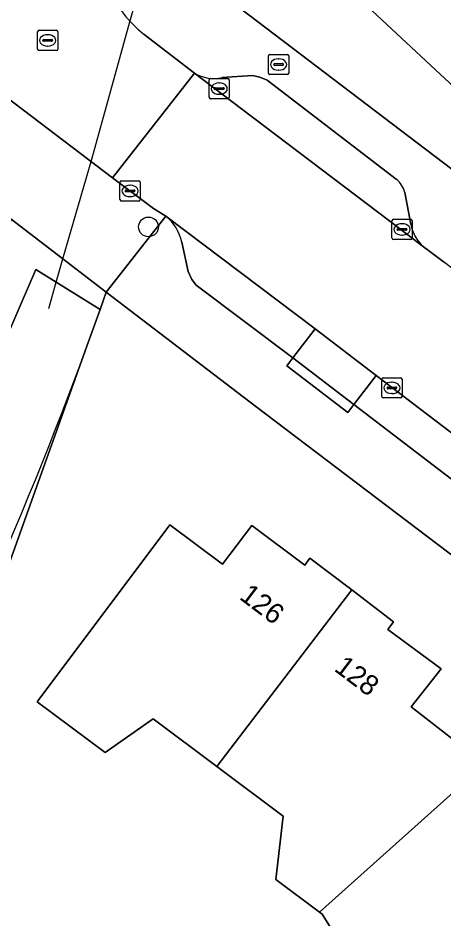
# Model space of a CAD drawing. Extents: x 159626 to 160723, y 388173 to 389416.
# Drawn here: x 160440.65 to 160461.73, y 388606.29 to 388650.92 of the extents above; entities that cross this region are included whole.
import ezdxf

# ---------------------------------------------------------------- set-up
doc = ezdxf.new("R2010")
doc.units = 0
for name, color, linetype in [('IMGEO_Berm_groen', 7, 'Continuous'), ('IMGEO_Boom', 7, 'Continuous'), ('IMGEO_Brandkraan', 7, 'Continuous'), ('IMGEO_Duiker', 7, 'Continuous'), ('IMGEO_Erf', 7, 'Continuous'), ('IMGEO_Kolk', 7, 'Continuous'), ('IMGEO_Pand', 7, 'Continuous'), ('IMGEO_Pand_nummerreeks', 7, 'Continuous'), ('IMGEO_Parkeervlak_open', 7, 'Continuous'), ('IMGEO_Rijbaan_lokaal_gesloten', 7, 'Continuous'), ('IMGEO_Rijbaan_lokaal_open', 7, 'Continuous'), ('IMGEO_Rioolput', 7, 'Continuous'), ('IMGEO_Voetpad_open', 7, 'Continuous'), ('IMGEO_Waterloop', 7, 'Continuous')]:
    doc.layers.add(name, color=color, linetype=linetype)

msp = doc.modelspace()

# ---------------------------------------------------------------- linework, layer by layer
at = {"layer": 'IMGEO_Berm_groen'}
for points in [[(160429.634, 388610.908), (160441.529, 388638.466), (160442.538, 388637.837), (160444.706, 388636.484), (160445.015, 388637.348), (160442.866, 388638.996), (160440.306, 388640.958), (160440.14, 388640.514), (160439.973, 388640.071)], [(160426.76, 388595.873), (160434.06, 388609.33), (160439.82, 388622.82), (160444.055, 388634.663)]]:
    msp.add_lwpolyline(points, dxfattribs=at)
msp.add_arc((160271.208, 388697.491), 183.911, 331.19029, 340.02424, dxfattribs=at)
at = {"layer": 'IMGEO_Boom'}
msp.add_circle((160447.102, 388640.575), 0.489, dxfattribs=at)
at = {"layer": 'IMGEO_Brandkraan'}
for p, q in [((160453.041, 388648.195), (160453.041, 388649.047)), ((160453.116, 388649.121), (160453.968, 388649.121)), ((160453.529, 388648.901), (160453.554, 388648.901)), ((160454.042, 388649.047), (160454.042, 388648.195)), ((160453.3, 388648.615), (160453.3, 388648.627)), ((160453.738, 388648.578), (160453.34, 388648.578)), ((160453.343, 388648.664), (160453.741, 388648.664)), ((160453.552, 388648.341), (160453.527, 388648.341)), ((160453.784, 388648.627), (160453.784, 388648.615)), ((160453.968, 388648.121), (160453.116, 388648.121))]:
    msp.add_line(p, q, dxfattribs=at)
for points in [[(160453.041, 388648.195), (160453.041, 388649.047)], [(160453.116, 388649.121), (160453.968, 388649.121)], [(160454.042, 388649.047), (160454.042, 388648.195)], [(160453.968, 388648.121), (160453.116, 388648.121)]]:
    msp.add_lwpolyline(points, dxfattribs=at)
for centre, radius, start, end in [((160453.118, 388649.045), 0.0765, 91.552, 178.448), ((160453.118, 388649.045), 0.0765, 91.552, 178.448), ((160453.966, 388649.045), 0.0765, 1.552, 88.448), ((160453.966, 388649.045), 0.0765, 1.552, 88.448), ((160453.34, 388648.624), 0.0403, 85.8775, 175.7526), ((160453.337, 388648.614), 0.0366, 178.938, 274.7102), ((160453.741, 388648.621), 0.043, 264.8664, 352.4533), ((160453.745, 388648.626), 0.0386, 1.7309, 96.639), ((160453.118, 388648.197), 0.0765, 181.552, 268.448), ((160453.118, 388648.197), 0.0765, 181.552, 268.448), ((160453.966, 388648.197), 0.0765, 271.552, 358.448), ((160453.966, 388648.197), 0.0765, 271.552, 358.448)]:
    msp.add_arc(centre, radius, start, end, dxfattribs=at)
for centre, major_axis, ratio, start_param, end_param in [((160453.528, 388648.621), (-0.387, 0.002), 0.722429, 4.712389, 7.853982), ((160453.553, 388648.621), (-0.39, 0.002), 0.717154, 1.570796, 4.712389)]:
    msp.add_ellipse(centre, major_axis=major_axis, ratio=ratio, start_param=start_param, end_param=end_param, dxfattribs=at)
at = {"layer": 'IMGEO_Duiker'}
msp.add_lwpolyline([(160442.168, 388636.53), (160442.538, 388637.837), (160442.866, 388638.996), (160444.292, 388643.932), (160446.185, 388650.731), (160447.311, 388654.712), (160447.539, 388655.517), (160447.651, 388655.912)], dxfattribs=at)
at = {"layer": 'IMGEO_Erf'}
for points in [[(160464.967, 388644.948), (160461.313, 388648.361), (160455.028, 388654.227), (160460.023, 388659.588), (160459.203, 388660.352), (160462.612, 388664.011)], [(160448.508, 388655.087), (160448.24, 388654.005), (160450.027, 388652.645), (160464.587, 388641.545)], [(160473.922, 388615.363), (160452.411, 388631.678), (160445.015, 388637.348), (160444.706, 388636.484), (160444.055, 388634.663), (160439.82, 388622.82), (160434.06, 388609.33), (160426.76, 388595.873), (160418.317, 388583.095), (160421.291, 388580.817), (160422.334, 388579.975)], [(160462.556, 388600.786), (160460.41, 388604.216), (160457.583, 388603.522), (160455.705, 388606.522), (160455.569, 388606.624), (160453.408, 388608.239), (160453.774, 388611.386), (160450.491, 388613.842), (160447.336, 388616.202), (160444.953, 388614.537), (160441.598, 388617.047), (160448.158, 388625.814), (160450.768, 388623.86), (160452.211, 388625.789), (160454.837, 388623.823), (160455.094, 388624.167), (160457.163, 388622.589), (160459.23, 388621.012), (160458.945, 388620.624), (160461.592, 388618.682), (160460.1, 388616.798), (160463.747, 388613.959)]]:
    msp.add_lwpolyline(points, dxfattribs=at)
at = {"layer": 'IMGEO_Kolk'}
for p, q in [((160450.102, 388647.001), (160450.102, 388647.853)), ((160450.177, 388647.927), (160451.029, 388647.927)), ((160451.103, 388647.853), (160451.103, 388647.001)), ((160450.361, 388647.421), (160450.361, 388647.433)), ((160450.799, 388647.384), (160450.401, 388647.384)), ((160450.404, 388647.47), (160450.802, 388647.47)), ((160450.59, 388647.707), (160450.615, 388647.707)), ((160450.845, 388647.433), (160450.845, 388647.421)), ((160451.029, 388646.927), (160450.177, 388646.927)), ((160450.613, 388647.147), (160450.588, 388647.147)), ((160445.69, 388641.932), (160445.69, 388642.784)), ((160445.765, 388642.858), (160446.617, 388642.858)), ((160446.178, 388642.638), (160446.203, 388642.638)), ((160446.691, 388642.784), (160446.691, 388641.932)), ((160445.949, 388642.352), (160445.949, 388642.364)), ((160446.387, 388642.315), (160445.989, 388642.315)), ((160445.992, 388642.401), (160446.39, 388642.401)), ((160446.201, 388642.078), (160446.176, 388642.078)), ((160446.433, 388642.364), (160446.433, 388642.352)), ((160446.617, 388641.858), (160445.765, 388641.858)), ((160459.152, 388640.026), (160459.152, 388640.878)), ((160459.227, 388640.952), (160460.079, 388640.952)), ((160459.64, 388640.732), (160459.665, 388640.732)), ((160460.153, 388640.878), (160460.153, 388640.026)), ((160459.411, 388640.446), (160459.411, 388640.458)), ((160459.849, 388640.409), (160459.451, 388640.409)), ((160459.454, 388640.495), (160459.852, 388640.495)), ((160459.895, 388640.458), (160459.895, 388640.446)), ((160460.079, 388639.952), (160459.227, 388639.952)), ((160459.663, 388640.172), (160459.638, 388640.172)), ((160458.725, 388633.1), (160459.577, 388633.1)), ((160458.65, 388632.174), (160458.65, 388633.026)), ((160458.952, 388632.643), (160459.35, 388632.643)), ((160459.138, 388632.88), (160459.163, 388632.88)), ((160459.651, 388633.026), (160459.651, 388632.174)), ((160458.909, 388632.594), (160458.909, 388632.606)), ((160459.347, 388632.557), (160458.949, 388632.557)), ((160459.161, 388632.32), (160459.136, 388632.32)), ((160459.393, 388632.606), (160459.393, 388632.594)), ((160459.577, 388632.1), (160458.725, 388632.1))]:
    msp.add_line(p, q, dxfattribs=at)
for points in [[(160450.102, 388647.001), (160450.102, 388647.853)], [(160450.177, 388647.927), (160451.029, 388647.927)], [(160451.103, 388647.853), (160451.103, 388647.001)], [(160451.029, 388646.927), (160450.177, 388646.927)], [(160445.69, 388641.932), (160445.69, 388642.784)], [(160445.765, 388642.858), (160446.617, 388642.858)], [(160446.691, 388642.784), (160446.691, 388641.932)], [(160446.617, 388641.858), (160445.765, 388641.858)], [(160459.152, 388640.026), (160459.152, 388640.878)], [(160459.227, 388640.952), (160460.079, 388640.952)], [(160460.153, 388640.878), (160460.153, 388640.026)], [(160460.079, 388639.952), (160459.227, 388639.952)], [(160458.725, 388633.1), (160459.577, 388633.1)], [(160458.65, 388632.174), (160458.65, 388633.026)], [(160459.651, 388633.026), (160459.651, 388632.174)], [(160459.577, 388632.1), (160458.725, 388632.1)]]:
    msp.add_lwpolyline(points, dxfattribs=at)
for centre, radius, start, end in [((160450.179, 388647.851), 0.0765, 91.552, 178.448), ((160450.179, 388647.851), 0.0765, 91.552, 178.448), ((160451.027, 388647.851), 0.0765, 1.552, 88.448), ((160451.027, 388647.851), 0.0765, 1.552, 88.448), ((160450.401, 388647.43), 0.0403, 85.8775, 175.7526), ((160450.398, 388647.42), 0.0366, 178.938, 274.7102), ((160450.802, 388647.427), 0.043, 264.8664, 352.4533), ((160450.806, 388647.432), 0.0386, 1.7309, 96.639), ((160450.179, 388647.003), 0.0765, 181.552, 268.448), ((160450.179, 388647.003), 0.0765, 181.552, 268.448), ((160451.027, 388647.003), 0.0765, 271.552, 358.448), ((160451.027, 388647.003), 0.0765, 271.552, 358.448), ((160445.767, 388642.782), 0.0765, 91.552, 178.448), ((160445.767, 388642.782), 0.0765, 91.552, 178.448), ((160446.615, 388642.782), 0.0765, 1.552, 88.448), ((160446.615, 388642.782), 0.0765, 1.552, 88.448), ((160445.989, 388642.361), 0.0403, 85.8775, 175.7526), ((160445.986, 388642.351), 0.0366, 178.938, 274.7102), ((160446.39, 388642.358), 0.043, 264.8664, 352.4533), ((160446.394, 388642.363), 0.0386, 1.7309, 96.639), ((160445.767, 388641.934), 0.0765, 181.552, 268.448), ((160445.767, 388641.934), 0.0765, 181.552, 268.448), ((160446.615, 388641.934), 0.0765, 271.552, 358.448), ((160446.615, 388641.934), 0.0765, 271.552, 358.448), ((160459.229, 388640.876), 0.0765, 91.552, 178.448), ((160459.229, 388640.876), 0.0765, 91.552, 178.448), ((160460.077, 388640.876), 0.0765, 1.552, 88.448), ((160460.077, 388640.876), 0.0765, 1.552, 88.448), ((160459.451, 388640.455), 0.0403, 85.8775, 175.7526), ((160459.448, 388640.445), 0.0366, 178.938, 274.7102), ((160459.852, 388640.452), 0.043, 264.8664, 352.4533), ((160459.856, 388640.457), 0.0386, 1.7309, 96.639), ((160459.229, 388640.028), 0.0765, 181.552, 268.448), ((160459.229, 388640.028), 0.0765, 181.552, 268.448), ((160460.077, 388640.028), 0.0765, 271.552, 358.448), ((160460.077, 388640.028), 0.0765, 271.552, 358.448), ((160458.727, 388633.024), 0.0765, 91.552, 178.448), ((160458.727, 388633.024), 0.0765, 91.552, 178.448), ((160459.575, 388633.024), 0.0765, 1.552, 88.448), ((160459.575, 388633.024), 0.0765, 1.552, 88.448), ((160458.949, 388632.603), 0.0403, 85.8775, 175.7526), ((160459.354, 388632.605), 0.0386, 1.7309, 96.639), ((160458.946, 388632.593), 0.0366, 178.938, 274.7102), ((160459.35, 388632.6), 0.043, 264.8664, 352.4533), ((160458.727, 388632.176), 0.0765, 181.552, 268.448), ((160458.727, 388632.176), 0.0765, 181.552, 268.448), ((160459.575, 388632.176), 0.0765, 271.552, 358.448), ((160459.575, 388632.176), 0.0765, 271.552, 358.448)]:
    msp.add_arc(centre, radius, start, end, dxfattribs=at)
for centre, major_axis, ratio, start_param, end_param in [((160450.589, 388647.427), (-0.387, 0.002), 0.722429, 4.712389, 7.853982), ((160450.614, 388647.427), (-0.39, 0.002), 0.717154, 1.570796, 4.712389), ((160446.177, 388642.358), (-0.387, 0.002), 0.722429, 4.712389, 7.853982), ((160446.202, 388642.358), (-0.39, 0.002), 0.717154, 1.570796, 4.712389), ((160459.639, 388640.452), (-0.387, 0.002), 0.722429, 4.712389, 7.853982), ((160459.664, 388640.452), (-0.39, 0.002), 0.717154, 1.570796, 4.712389), ((160459.137, 388632.6), (-0.387, 0.002), 0.722429, 4.712389, 7.853982), ((160459.162, 388632.6), (-0.39, 0.002), 0.717154, 1.570796, 4.712389)]:
    msp.add_ellipse(centre, major_axis=major_axis, ratio=ratio, start_param=start_param, end_param=end_param, dxfattribs=at)
at = {"layer": 'IMGEO_Pand'}
for points in [[(160471.835, 388655.659), (160471.955, 388655.754), (160462.835, 388664.25), (160462.612, 388664.011), (160459.203, 388660.352), (160460.023, 388659.588), (160455.028, 388654.227), (160461.313, 388648.361), (160464.967, 388644.948), (160470.181, 388650.532), (160468.521, 388652.097), (160470.903, 388654.657)], [(160450.491, 388613.842), (160457.163, 388622.589), (160455.094, 388624.167), (160454.837, 388623.823), (160452.211, 388625.789), (160450.768, 388623.86), (160448.158, 388625.814), (160441.598, 388617.047), (160444.953, 388614.537), (160447.336, 388616.202)], [(160450.491, 388613.842), (160453.774, 388611.386), (160453.408, 388608.239), (160455.569, 388606.624), (160463.747, 388613.959), (160460.1, 388616.798), (160461.592, 388618.682), (160458.945, 388620.624), (160459.23, 388621.012), (160457.163, 388622.589)], [(160463.747, 388613.959), (160455.569, 388606.624), (160455.705, 388606.522), (160457.583, 388603.522), (160460.41, 388604.216), (160462.556, 388600.786), (160471.743, 388606.531), (160470.359, 388608.742), (160469.995, 388608.514), (160468.256, 388611.295), (160466.213, 388610.017)]]:
    msp.add_lwpolyline(points, close=True, dxfattribs=at)
at = {"layer": 'IMGEO_Parkeervlak_open'}
for points in [[(160449.379, 388648.196), (160451.702, 388646.423), (160459.596, 388640.453), (160460.712, 388639.589)], [(160459.361, 388642.94), (160452.979, 388647.838), (160452.614, 388647.988), (160452.258, 388648.07), (160450.745, 388647.969)], [(160460.082, 388640.712), (160459.789, 388642.287)], [(160448.745, 388639.816), (160449.059, 388638.37), (160449.24, 388637.977), (160449.456, 388637.696), (160454.246, 388634.083), (160455.348, 388635.527), (160447.964, 388641.112)]]:
    msp.add_lwpolyline(points, dxfattribs=at)
for points in [[(160455.348, 388635.527), (160454.246, 388634.083), (160457.268, 388631.77), (160458.374, 388633.219)], [(160458.374, 388633.219), (160457.268, 388631.77), (160466.036, 388625.067), (160467.149, 388626.526)]]:
    msp.add_lwpolyline(points, close=True, dxfattribs=at)
for centre, radius, start, end in [((160450.339, 388649.748), 1.825, 238.267, 282.8627), ((160458.629, 388641.993), 1.197, 14.2044, 52.2802), ((160446.513, 388639.354), 2.279, 11.6885, 50.4598), ((160462.065, 388641.086), 2.018, 190.6917, 227.8929)]:
    msp.add_arc(centre, radius, start, end, dxfattribs=at)
at = {"layer": 'IMGEO_Rijbaan_lokaal_gesloten'}
msp.add_lwpolyline([(160480.726, 388624.386), (160479.761, 388625.134), (160479.475, 388625.34), (160463.293, 388637.64), (160461.761, 388638.812), (160460.956, 388639.4), (160460.712, 388639.589), (160459.596, 388640.453), (160451.702, 388646.423), (160449.379, 388648.196), (160445.327, 388643.009), (160447.348, 388641.481), (160447.964, 388641.112), (160455.348, 388635.527), (160458.374, 388633.219), (160467.149, 388626.526), (160470.17, 388624.222), (160475.385, 388620.244), (160477.279, 388618.799)], dxfattribs=at)
at = {"layer": 'IMGEO_Rijbaan_lokaal_open'}
msp.add_lwpolyline([(160435.247, 388658.875), (160434.926, 388659.154), (160430.911, 388653.976), (160445.327, 388643.009), (160449.379, 388648.196), (160446.896, 388650.101)], dxfattribs=at)
msp.add_arc((160450.597, 388654.787), 5.971, 168.5893, 231.6965, dxfattribs=at)
at = {"layer": 'IMGEO_Rioolput'}
for p, q in [((160441.612, 388649.388), (160441.612, 388650.24)), ((160441.687, 388650.314), (160442.539, 388650.314)), ((160442.1, 388650.094), (160442.125, 388650.094)), ((160442.613, 388650.24), (160442.613, 388649.388)), ((160441.871, 388649.808), (160441.871, 388649.82)), ((160442.309, 388649.771), (160441.911, 388649.771)), ((160441.914, 388649.857), (160442.312, 388649.857)), ((160442.355, 388649.82), (160442.355, 388649.808)), ((160442.539, 388649.314), (160441.687, 388649.314)), ((160442.123, 388649.534), (160442.098, 388649.534))]:
    msp.add_line(p, q, dxfattribs=at)
for points in [[(160441.612, 388649.388), (160441.612, 388650.24)], [(160441.687, 388650.314), (160442.539, 388650.314)], [(160442.613, 388650.24), (160442.613, 388649.388)], [(160442.539, 388649.314), (160441.687, 388649.314)]]:
    msp.add_lwpolyline(points, dxfattribs=at)
for centre, radius, start, end in [((160441.689, 388650.238), 0.0765, 91.552, 178.448), ((160441.689, 388650.238), 0.0765, 91.552, 178.448), ((160442.537, 388650.238), 0.0765, 1.552, 88.448), ((160442.537, 388650.238), 0.0765, 1.552, 88.448), ((160441.911, 388649.817), 0.0403, 85.8775, 175.7526), ((160441.908, 388649.807), 0.0366, 178.938, 274.7102), ((160442.312, 388649.814), 0.043, 264.8664, 352.4533), ((160442.316, 388649.819), 0.0386, 1.7309, 96.639), ((160441.689, 388649.39), 0.0765, 181.552, 268.448), ((160441.689, 388649.39), 0.0765, 181.552, 268.448), ((160442.537, 388649.39), 0.0765, 271.552, 358.448), ((160442.537, 388649.39), 0.0765, 271.552, 358.448)]:
    msp.add_arc(centre, radius, start, end, dxfattribs=at)
for centre, major_axis, ratio, start_param, end_param in [((160442.099, 388649.814), (-0.387, 0.002), 0.722429, 4.712389, 7.853982), ((160442.124, 388649.814), (-0.39, 0.002), 0.717154, 1.570796, 4.712389)]:
    msp.add_ellipse(centre, major_axis=major_axis, ratio=ratio, start_param=start_param, end_param=end_param, dxfattribs=at)
at = {"layer": 'IMGEO_Voetpad_open'}
for points in [[(160387.612, 388681.185), (160432.389, 388646.917), (160432.882, 388646.546), (160434.385, 388645.415), (160436.965, 388643.472), (160440.306, 388640.958), (160442.866, 388638.996), (160445.015, 388637.348), (160447.964, 388641.112), (160447.348, 388641.481), (160445.327, 388643.009), (160430.911, 388653.976), (160428.883, 388655.496)], [(160464.587, 388641.545), (160450.027, 388652.645)], [(160446.896, 388650.101), (160449.379, 388648.196)], [(160450.745, 388647.969), (160452.258, 388648.07), (160452.614, 388647.988), (160452.979, 388647.838), (160459.361, 388642.94)], [(160459.789, 388642.287), (160460.082, 388640.712)], [(160447.964, 388641.112), (160445.015, 388637.348), (160452.411, 388631.678), (160473.922, 388615.363)], [(160477.267, 388616.407), (160476.915, 388616.037), (160473.963, 388618.356), (160474.264, 388618.777), (160469.055, 388622.759), (160468.745, 388622.352), (160465.721, 388624.654), (160466.036, 388625.067), (160457.268, 388631.77), (160456.965, 388631.373), (160453.942, 388633.685), (160454.246, 388634.083), (160449.456, 388637.696), (160449.24, 388637.977), (160449.059, 388638.37), (160448.745, 388639.816)], [(160460.712, 388639.589), (160460.956, 388639.4), (160461.761, 388638.812)]]:
    msp.add_lwpolyline(points, dxfattribs=at)
msp.add_lwpolyline([(160454.246, 388634.083), (160453.942, 388633.685), (160456.965, 388631.373), (160457.268, 388631.77)], close=True, dxfattribs=at)
for centre, radius, start, end in [((160450.597, 388654.787), 5.971, 168.5893, 231.6965), ((160450.339, 388649.748), 1.825, 238.267, 282.8627), ((160458.629, 388641.993), 1.197, 14.2044, 52.2802), ((160446.513, 388639.354), 2.279, 11.6885, 50.4598), ((160462.065, 388641.086), 2.018, 190.6917, 227.8929)]:
    msp.add_arc(centre, radius, start, end, dxfattribs=at)
at = {"layer": 'IMGEO_Waterloop'}
msp.add_lwpolyline([(160444.055, 388634.663), (160444.706, 388636.484), (160442.538, 388637.837), (160441.529, 388638.466), (160429.634, 388610.908)], dxfattribs=at)
msp.add_arc((160271.208, 388697.491), 183.911, 331.19029, 340.02424, dxfattribs=at)

# ---------------------------------------------------------------- texts
at = {"layer": 'IMGEO_Pand_nummerreeks'}
for s, p in [('126', (160451.549, 388622.175)), ('128', (160456.244, 388618.619))]:
    msp.add_text(s, height=1, rotation=322.8526, dxfattribs=at).set_placement(p)

doc.saveas('drawing.dxf')
